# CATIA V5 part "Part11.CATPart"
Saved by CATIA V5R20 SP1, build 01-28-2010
Part number: vis_réglage
Bounding box of the stored display mesh (mm): x 58.9 to 61.1, y -11.1 to -8.9, z 0 to 16
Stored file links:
  F:\Pro\Emplois\1_Chercheur\ThinkMOTION\MMS\MMS_GR1\abruchon\Catia\Part11.CATPart
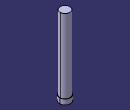
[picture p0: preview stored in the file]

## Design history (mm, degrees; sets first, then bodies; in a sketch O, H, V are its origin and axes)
Body1 (main body)
  Sketch1 on xy-plane, origin (0, 0, 0), H (1, 0, 0), V (0, 1, 0)
    circle A1 centre (60, -10) radius 1.1
    radius A1 = 1.1
  Pad1: profile Sketch1, direction (0, 0, 1), length 16
  Sketch2 on end face of Pad1, origin (0, 0, 16), H (1, 0, 0), V (0, 1, 0)
    circle A1 centre (60, -10) radius 1
    reference projected circle E1 centre (60, -10) radius 1.1 from edge [face of Pad1 from Sketch1.A1 | end face of Pad1]
    radius A1 = 1
    concentricity: A1 E1
  Pocket1: profile Sketch2, direction (0, 0, -1), length 15, outer side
